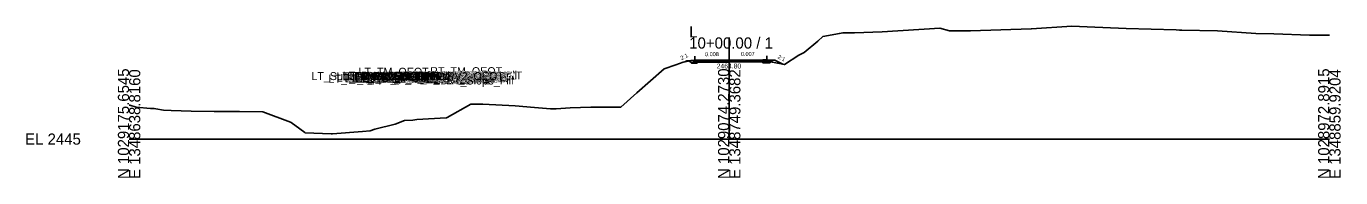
# Model space of a CAD drawing. Extents: x -26 to 1453, y -10 to 4527.
# Drawn here: x -25.7 to 302.8, y -9.7 to 28.3 of the extents above; entities that cross this region are included whole.
import ezdxf

# ---------------------------------------------------------------- set-up
doc = ezdxf.new("R2010")
doc.units = 0
for name, color, linetype in [('Default', 7, 'Continuous'), ('Exist CMT Pavement', 7, 'Continuous'), ('Exist Cross Section Cell', 7, 'Continuous'), ('Exist XS Center Line Elevation Label', 7, 'Continuous'), ('Exist XS Ground Line', 7, 'Continuous'), ('Prop CMT Pvmt Course 1', 7, 'Continuous'), ('Prop CMT Pvmt Course 2', 7, 'Continuous'), ('Prop CMT Pvmt Course 3', 7, 'Continuous'), ('Prop CMT Pvmt Surface', 7, 'Continuous'), ('Prop CMT Pvmt Surface Shoulder', 7, 'Continuous'), ('Prop CMT Pvmt Wedge Surface 1', 7, 'Continuous'), ('Prop CMT Pvmt Wedge Surface 2', 7, 'Continuous'), ('Prop CMT Pvmt Wedge Surface 3', 7, 'Continuous'), ('Prop CMT Shld Paved Course 1', 7, 'Continuous'), ('Prop CMT Shld Paved Course 2', 7, 'Continuous'), ('Prop CMT Shld Paved Course 3', 7, 'Continuous'), ('Prop CMT Slope Grass', 7, 'Continuous'), ('Prop CMT Subgrade Earthwork', 7, 'Continuous'), ('Prop XS Earthwork Shape', 7, 'Continuous'), ('Prop XS EOT Tick Mark', 7, 'Continuous'), ('Prop XS SE Text', 7, 'Continuous'), ('Prop XS Side Slope Text', 7, 'Continuous')]:
    doc.layers.add(name, color=color, linetype=linetype)

msp = doc.modelspace()

# ---------------------------------------------------------------- linework, layer by layer
at = {"layer": 'Exist CMT Pavement'}
for points in [[(150, 19.8), (149.1, 19.79), (148.39, 19.78), (145.96, 19.77), (142.82, 19.74), (141.92, 19.73)], [(150, 19.8), (150.06, 19.8), (150.93, 19.79), (154.18, 19.77), (157.44, 19.75), (157.61, 19.75), (158.37, 19.74)]]:
    msp.add_lwpolyline(points, dxfattribs=at)
at = {"layer": 'Exist Cross Section Cell'}
for p, q in [((150, 0), (150, 25.46)), ((0, 0), (150, 0)), ((150, 0), (300, 0))]:
    msp.add_line(p, q, dxfattribs=at)
at = {"layer": 'Exist XS Ground Line'}
msp.add_lwpolyline([(0, 8.46), (0.19, 8.49), (1.74, 8.03), (5.37, 7.67), (6.08, 7.67), (6.23, 7.65), (6.72, 7.54), (8.59, 7.24), (10.55, 7.17), (15.54, 6.98), (21.25, 6.88), (27.63, 6.9), (33.41, 6.85), (40.37, 4.25), (40.5, 4.14), (42.68, 2.54), (43.96, 1.62), (43.99, 1.59), (50.5, 1.27), (50.81, 1.27), (58.31, 1.91), (60.23, 2.05), (61.4, 2.46), (66.54, 3.73), (68.88, 4.66), (70.94, 4.74), (71.96, 4.87), (79.24, 5.34), (79.35, 5.35), (79.42, 5.35), (79.52, 5.41), (85.39, 8.73), (88.39, 8.73), (96.48, 8.32), (101.32, 7.88), (105.32, 7.54), (106.73, 7.56), (110.21, 7.81), (115.38, 7.97), (120.64, 8.02), (122.91, 8.01), (126.95, 11.62), (133.75, 17.57), (136.68, 18.62), (138.5, 19.25), (140.23, 19.61), (141.47, 19.73), (148.39, 19.78), (150, 19.8), (150.06, 19.8), (157.61, 19.75), (159.37, 19.72), (160.11, 19.54), (160.81, 19.24), (163.81, 18.67), (167.42, 21.05), (168.74, 21.72), (172.17, 24.51), (173.44, 25.68), (177.54, 26.45), (178.38, 26.57), (181.34, 26.63), (188.27, 26.89), (202.64, 27.75), (205.03, 27.12), (206.28, 27.09), (209.66, 27.14), (210.27, 27.14), (225.43, 27.6), (225.59, 27.61), (235.62, 28.25), (239.5, 28.15), (249.2, 27.68), (261.68, 27.33), (262.54, 27.29), (262.7, 27.28), (263.11, 27.26), (272.01, 27.13), (281.63, 26.42), (286.14, 26.39), (295.06, 26.03), (300, 26.03)], dxfattribs=at)
at = {"layer": 'Prop CMT Pvmt Course 1'}
for points in [[(150, 19.8), (141.42, 19.73)], [(141.42, 19.73), (141.42, 19.48)], [(150, 19.8), (159.37, 19.87)], [(150, 19.67), (150, 19.8)], [(150, 19.67), (150, 19.8)], [(158.37, 19.73), (150, 19.67)], [(158.37, 19.61), (158.37, 19.73)], [(159.37, 19.87), (159.37, 19.62)], [(141.42, 19.48), (141.92, 19.49)], [(141.92, 19.61), (150, 19.67)], [(141.92, 19.49), (141.92, 19.61)], [(159.37, 19.62), (158.37, 19.61)]]:
    msp.add_lwpolyline(points, dxfattribs=at)
at = {"layer": 'Prop CMT Pvmt Course 2'}
for points in [[(141.92, 19.49), (141.42, 19.48)], [(141.42, 19.48), (141.42, 19.23)], [(141.42, 19.23), (141.92, 19.24)], [(141.92, 19.24), (141.92, 19.49)], [(158.37, 19.61), (159.37, 19.62)], [(158.37, 19.36), (158.37, 19.61)], [(159.37, 19.37), (158.37, 19.36)], [(159.37, 19.62), (159.37, 19.37)]]:
    msp.add_lwpolyline(points, dxfattribs=at)
at = {"layer": 'Prop CMT Pvmt Course 3'}
for points in [[(141.92, 19.24), (141.42, 19.23)], [(141.42, 19.23), (141.42, 18.98)], [(141.42, 18.98), (141.92, 18.99)], [(141.92, 18.99), (141.92, 19.24)], [(158.37, 19.36), (159.37, 19.37)], [(158.37, 19.11), (158.37, 19.36)], [(159.37, 19.12), (158.37, 19.11)], [(159.37, 19.37), (159.37, 19.12)]]:
    msp.add_lwpolyline(points, dxfattribs=at)
at = {"layer": 'Prop CMT Pvmt Surface'}
for points in [[(150, 19.8), (141.42, 19.73)], [(150, 19.8), (159.37, 19.87)]]:
    msp.add_lwpolyline(points, dxfattribs=at)
at = {"layer": 'Prop CMT Pvmt Surface Shoulder'}
for points in [[(141.42, 19.73), (141.42, 19.73)], [(159.37, 19.87), (159.37, 19.87)]]:
    msp.add_lwpolyline(points, dxfattribs=at)
at = {"layer": 'Prop CMT Pvmt Wedge Surface 1'}
for points in [[(141.92, 19.74), (141.42, 19.73)], [(141.92, 19.61), (141.92, 19.74)], [(150, 19.67), (158.37, 19.73)], [(158.37, 19.86), (159.37, 19.87)], [(158.37, 19.73), (158.37, 19.86)], [(150, 19.67), (141.92, 19.61)]]:
    msp.add_lwpolyline(points, dxfattribs=at)
at = {"layer": 'Prop CMT Pvmt Wedge Surface 2'}
for points in [[(141.42, 19.48), (141.42, 19.73)], [(159.37, 19.62), (159.37, 19.87)], [(150, 19.55), (141.92, 19.49), (141.42, 19.48)], [(150, 19.55), (158.37, 19.61), (159.37, 19.62)]]:
    msp.add_lwpolyline(points, dxfattribs=at)
at = {"layer": 'Prop CMT Pvmt Wedge Surface 3'}
for points in [[(141.42, 19.23), (141.42, 19.73)], [(159.37, 19.37), (159.37, 19.87)], [(150, 19.3), (141.92, 19.24), (141.42, 19.23)], [(150, 19.3), (158.37, 19.36), (159.37, 19.37)]]:
    msp.add_lwpolyline(points, dxfattribs=at)
at = {"layer": 'Prop CMT Shld Paved Course 1'}
for points in [[(141.42, 19.73), (141.42, 19.73), (141.16, 19.48)], [(141.42, 19.48), (141.42, 19.73)], [(159.37, 19.87), (159.37, 19.87), (159.62, 19.62)], [(159.37, 19.62), (159.37, 19.87)], [(141.16, 19.48), (141.42, 19.48)], [(159.62, 19.62), (159.37, 19.62)]]:
    msp.add_lwpolyline(points, dxfattribs=at)
at = {"layer": 'Prop CMT Shld Paved Course 2'}
for points in [[(141.42, 19.48), (141.16, 19.48), (140.91, 19.23)], [(140.91, 19.23), (141.42, 19.23)], [(141.42, 19.23), (141.42, 19.48)], [(159.37, 19.62), (159.62, 19.62), (159.87, 19.37)], [(159.37, 19.37), (159.37, 19.62)], [(159.87, 19.37), (159.37, 19.37)]]:
    msp.add_lwpolyline(points, dxfattribs=at)
at = {"layer": 'Prop CMT Shld Paved Course 3'}
for points in [[(140.91, 19.23), (140.66, 18.97)], [(140.66, 18.97), (141.42, 18.98)], [(141.42, 19.23), (140.91, 19.23)], [(140.91, 19.23), (140.91, 19.23)], [(141.42, 18.98), (141.42, 19.23)], [(159.37, 19.37), (159.87, 19.37)], [(159.37, 19.12), (159.37, 19.37)], [(160.12, 19.12), (159.37, 19.12)], [(159.87, 19.37), (159.87, 19.37)], [(159.87, 19.37), (160.12, 19.12)]]:
    msp.add_lwpolyline(points, dxfattribs=at)
at = {"layer": 'Prop CMT Slope Grass'}
for points in [[(141.42, 19.73), (139.42, 19.6)], [(159.37, 19.87), (161.37, 19.76)], [(161.37, 19.76), (163.4, 18.75)], [(139.42, 19.6), (138.89, 19.33)]]:
    msp.add_lwpolyline(points, dxfattribs=at)
at = {"layer": 'Prop CMT Subgrade Earthwork'}
for points in [[(141.92, 18.99), (141.92, 19.73)], [(158.37, 19.11), (158.37, 19.74)], [(160.12, 19.12), (160.79, 19.79)], [(140.66, 18.97), (140, 19.63)], [(141.42, 18.98), (140.66, 18.97)], [(141.92, 18.99), (141.42, 18.98)], [(158.37, 19.11), (159.37, 19.12)], [(159.37, 19.12), (160.12, 19.12)]]:
    msp.add_lwpolyline(points, dxfattribs=at)
at = {"layer": 'Prop XS Earthwork Shape'}
for points in [[(140.06, 19.57), (140.23, 19.61), (141.47, 19.73), (141.92, 19.73), (141.92, 18.99), (141.42, 18.98), (140.66, 18.97)], [(140.06, 19.57), (140.23, 19.61), (141.47, 19.73), (141.92, 19.73), (141.92, 18.99), (141.42, 18.98), (140.66, 18.97)], [(160.11, 19.54), (160.41, 19.41), (160.12, 19.12), (159.37, 19.12), (158.37, 19.11), (158.37, 19.74), (159.37, 19.72)], [(160.11, 19.54), (160.41, 19.41), (160.12, 19.12), (159.37, 19.12), (158.37, 19.11), (158.37, 19.74), (159.37, 19.72)], [(160.41, 19.41), (160.81, 19.24), (163.4, 18.75), (161.37, 19.76), (160.79, 19.79)], [(160.41, 19.41), (160.81, 19.24), (163.4, 18.75), (161.37, 19.76), (160.79, 19.79)], [(140.06, 19.57), (140, 19.63), (139.42, 19.6), (138.89, 19.33)], [(140.06, 19.57), (140, 19.63), (139.42, 19.6), (138.89, 19.33)]]:
    msp.add_lwpolyline(points, close=True, dxfattribs=at)
at = {"layer": 'Prop XS EOT Tick Mark'}
for points in [[(141.42, 19.73), (141.42, 20.73)], [(159.37, 19.87), (159.37, 20.87)]]:
    msp.add_lwpolyline(points, dxfattribs=at)

# ---------------------------------------------------------------- texts
at = {"layer": 'Default'}
for s, height, p in [('LT_Sub_Trench_Out_DLT', 2, (45.57, 14.77)), ('LT_PV_Sub_Tie_Out', 2, (51.87, 14.73)), ('LT_PS3_Shelf_Out', 2, (51.9, 14.36)), ('LT_PV_EG_TestPt3', 2, (53.33, 14.74)), ('LT_PV1_OEEOP_Null', 2, (53.38, 14.87)), ('LT_GS_OS_CTL', 2, (53.79, 14.73)), ('LT_PV_OEEOP_EG', 2, (54.47, 14.73)), ('LT_PV1_OEEOP_W', 2, (54.91, 14.74)), ('LT_PV2_OEEOP', 2, (56.23, 14.62)), ('LT_PS2_OEOP', 2, (56.4, 14.61)), ('LT_PV_EG_TestPt2', 2, (56.47, 14.77)), ('LT_PV2_OEOT', 2, (56.59, 14.61)), ('LT_PV1_OEOT', 2, (57.16, 14.86)), ('LT_PS1_OEOP', 2, (57.22, 14.86)), ('LT_TM_OEOT', 2, (57.36, 15.86)), ('LT_PV_EG_TestPt1', 2, (60.18, 14.79)), ('RT_PV_EG_TestPt1', 2, (61.96, 14.79)), ('RT_PV_EG_TestPt2', 2, (64.65, 14.77)), ('PV_EPGL_EG', 2, (66.24, 14.8)), ('RT_Sub_Trench_Out_DLT', 2, (66.31, 14.92)), ('PV2_PGL_W', 2, (67.02, 14.68)), ('PV3_PGL_W', 2, (67.02, 14.43)), ('PV1_PGL_W', 2, (67.58, 14.81)), ('RT_PV_EG_TestPt3', 2, (67.91, 14.75)), ('RT_PV_Sub_Tie_Out', 2, (68.27, 14.74)), ('PV1_PGL', 2, (69.47, 14.93)), ('RT_PV1_OEEOP_Null', 2, (69.78, 14.99)), ('RT_PS3_Shelf_Out', 2, (70.81, 14.5)), ('RT_PV_OEEOP_EG', 2, (70.87, 14.74)), ('RT_PV1_OEEOP_W', 2, (71.31, 14.86)), ('RT_PV2_OEEOP', 2, (72.63, 14.74)), ('RT_PV3_OEEOP', 2, (72.63, 14.49)), ('RT_PV2_OEOT', 2, (74.5, 14.75)), ('RT_PV3_OEOT', 2, (74.5, 14.5)), ('RT_PS2_OEOP', 2, (74.81, 14.75)), ('RT_PV1_OEOT', 2, (75.06, 15)), ('RT_PS3_OEOP', 2, (75.06, 14.5)), ('RT_PS1_OEOP', 2, (75.13, 15)), ('RT_TM_OEOT', 2, (75.27, 16)), ('RT_GS_OS_CTL', 2, (75.69, 14.89)), ('LT_Sub_Trench_Out', 2, (49.86, 14.11)), ('LT_Slope_Fill', 2, (53.92, 14.22)), ('LT_Sub_OEEOP', 2, (56.13, 14.12)), ('LT_PS3_OEOP', 2, (56.15, 14.36)), ('LT_PV3_OEEOP', 2, (56.23, 14.37)), ('LT_Sub_OEOT', 2, (56.49, 14.11)), ('LT_PV3_OEOT', 2, (56.59, 14.36)), ('RT_Sub_Trench_Out', 2, (69.27, 14.25)), ('RT_Sub_OEEOP', 2, (72.54, 14.24)), ('RT_Sub_OEOT', 2, (74.4, 14.25)), ('RT_Slope_Fill', 2, (79.29, 13.67)), ('-', 0.0001, (0, 0)), ('-', 0.0001, (0, 0)), ('-', 0.0001, (0, 0)), ('-', 0.0001, (0, 0))]:
    msp.add_text(s, height=height, dxfattribs=at).set_placement(p)
at = {"layer": 'Exist Cross Section Cell'}
for s, p in [('L', (140, 25.46)), ('10+00.00 / 1', (140, 22.66)), ('EL 2445', (-26, -1.4))]:
    msp.add_text(s, height=2.8, dxfattribs=at).set_placement(p)
for s, p in [('N 1029175.6545', (0, -10)), ('E 1348638.8160', (2.8, -10)), ('N 1029074.2730', (150, -10)), ('E 1348749.3682', (152.8, -10)), ('N 1028972.8915', (300, -10)), ('E 1348859.9204', (302.8, -10))]:
    msp.add_text(s, height=2.8, rotation=90, dxfattribs=at).set_placement(p)
at = {"layer": 'Exist XS Center Line Elevation Label'}
msp.add_text('2464.80', height=1.23, dxfattribs=at).set_placement((146.86, 17.68))
at = {"layer": 'Prop XS SE Text'}
for s, rotation, p in [('0.008', 0.4584, (143.96, 20.75)), ('0.007', 0.4011, (152.92, 20.82))]:
    msp.add_text(s, height=1, rotation=rotation, dxfattribs=at).set_placement(p)
at = {"layer": 'Prop XS Side Slope Text'}
for rotation, p in [(26.5651, (138.11, 19.78)), (333.4349, (162.01, 20.28))]:
    msp.add_text('2:1', height=1, rotation=rotation, dxfattribs=at).set_placement(p)

doc.saveas('drawing.dxf')
